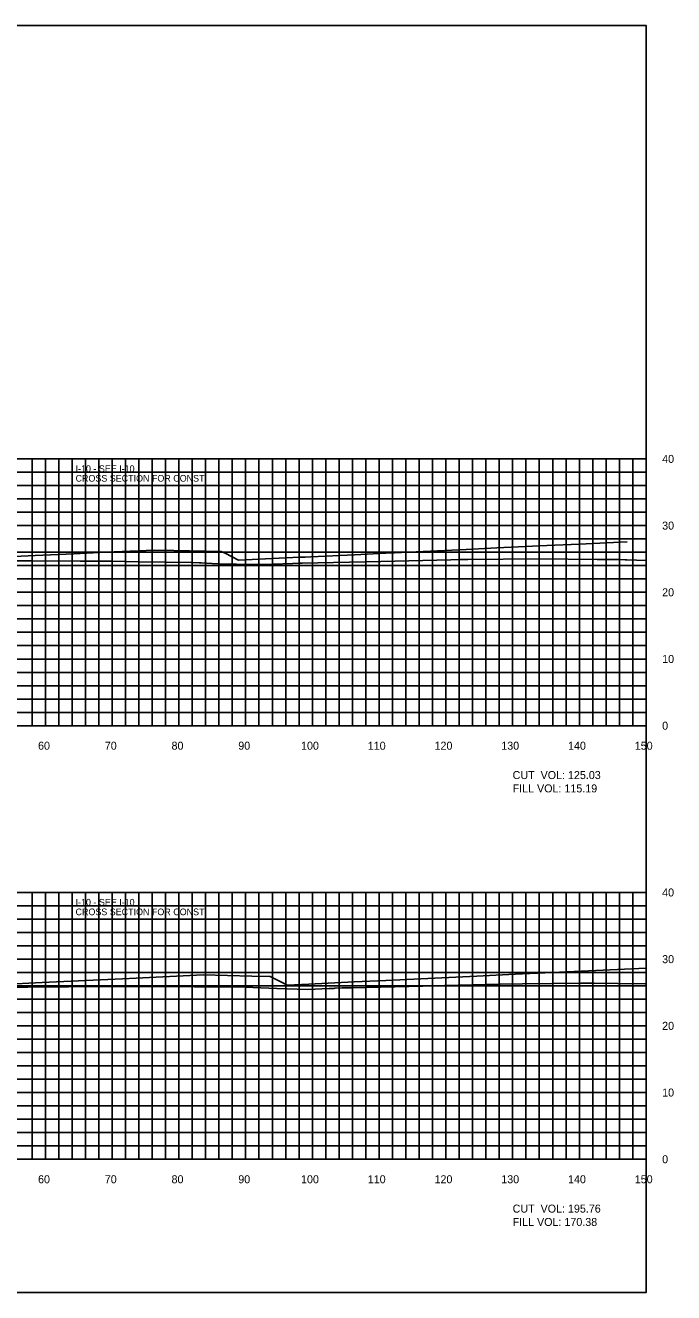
# Model space of a CAD drawing. Extents: x 1797652 to 1804159, y 242516 to 246906.
# Drawn here: x 1804061.5 to 1804158.6, y 242516 to 242706 of the extents above; entities that cross this region are included whole.
import ezdxf

# ---------------------------------------------------------------- set-up
doc = ezdxf.new("R2010")
doc.units = 0
for name, color, linetype in [('10', 7, 'Continuous'), ('3', 7, 'Continuous'), ('31', 7, 'Continuous'), ('60', 7, 'Continuous'), ('CL-CNST', 7, 'Continuous'), ('Level 62', 7, 'Continuous'), ('M-ROADS', 7, 'Continuous')]:
    doc.layers.add(name, color=color, linetype=linetype)

msp = doc.modelspace()

# ---------------------------------------------------------------- linework, layer by layer
msp.add_lwpolyline([(1803854.49, 242516), (1804154.49, 242516), (1804154.49, 242706), (1803854.49, 242706)], close=True)
at = {"layer": '60'}
for p, q in [((1804154.49, 242601), (1804154.49, 242641)), ((1804154.55, 242641), (1804154.49, 242641)), ((1804154.55, 242631), (1804154.49, 242631)), ((1804154.55, 242621), (1804154.49, 242621)), ((1804154.55, 242611), (1804154.49, 242611)), ((1803854.49, 242601), (1804154.49, 242601)), ((1804064.49, 242600.94), (1804064.49, 242601)), ((1804074.49, 242600.94), (1804074.49, 242601)), ((1804084.49, 242600.94), (1804084.49, 242601)), ((1804094.49, 242600.94), (1804094.49, 242601)), ((1804104.49, 242600.94), (1804104.49, 242601)), ((1804114.49, 242600.94), (1804114.49, 242601)), ((1804124.49, 242600.94), (1804124.49, 242601)), ((1804134.49, 242600.94), (1804134.49, 242601)), ((1804144.49, 242600.94), (1804144.49, 242601)), ((1804154.49, 242600.94), (1804154.49, 242601)), ((1804154.55, 242601), (1804154.49, 242601)), ((1804154.49, 242536), (1804154.49, 242576)), ((1804154.55, 242576), (1804154.49, 242576)), ((1804154.55, 242566), (1804154.49, 242566)), ((1804154.55, 242556), (1804154.49, 242556)), ((1804154.55, 242546), (1804154.49, 242546)), ((1803854.49, 242536), (1804154.49, 242536)), ((1804064.49, 242535.94), (1804064.49, 242536)), ((1804074.49, 242535.94), (1804074.49, 242536)), ((1804084.49, 242535.94), (1804084.49, 242536)), ((1804094.49, 242535.94), (1804094.49, 242536)), ((1804104.49, 242535.94), (1804104.49, 242536)), ((1804114.49, 242535.94), (1804114.49, 242536)), ((1804124.49, 242535.94), (1804124.49, 242536)), ((1804134.49, 242535.94), (1804134.49, 242536)), ((1804144.49, 242535.94), (1804144.49, 242536)), ((1804154.49, 242535.94), (1804154.49, 242536)), ((1804154.55, 242536), (1804154.49, 242536))]:
    msp.add_line(p, q, dxfattribs=at)
at = {"layer": 'CL-CNST'}
for points in [[(1804056.68, 242626.21), (1804062.96, 242626.5), (1804068.74, 242626.77), (1804073.61, 242627), (1804080.81, 242627.34), (1804083.71, 242627.27), (1804090.82, 242627.11), (1804091.42, 242626.85), (1804093.4, 242625.82), (1804102.54, 242626.25), (1804103.43, 242626.29), (1804104.27, 242626.33), (1804110.81, 242626.64), (1804115.49, 242626.86), (1804116.77, 242626.92), (1804127.55, 242627.43), (1804132.12, 242627.65), (1804139.61, 242628), (1804144.46, 242628.23), (1804151.67, 242628.57)], [(1804052.05, 242561.92), (1804063.99, 242562.49), (1804065.08, 242562.54), (1804076.06, 242563.06), (1804078.1, 242563.16), (1804088.13, 242563.64), (1804095.42, 242563.47), (1804098.18, 242563.41), (1804099.94, 242562.5), (1804100.7, 242562.11), (1804103.97, 242562.26), (1804110.76, 242562.59), (1804115.51, 242562.81), (1804122.82, 242563.16), (1804129.15, 242563.46), (1804134.89, 242563.73), (1804140.42, 242563.99), (1804146.96, 242564.3), (1804154.48, 242564.66), (1804154.49, 242564.66)]]:
    msp.add_lwpolyline(points, dxfattribs=at)
at = {"layer": 'Level 62'}
for p, q in [((1803854.49, 242641), (1804154.49, 242641)), ((1804062.49, 242601), (1804062.49, 242641)), ((1804064.49, 242601), (1804064.49, 242641)), ((1804066.49, 242601), (1804066.49, 242641)), ((1804068.49, 242601), (1804068.49, 242641)), ((1804070.49, 242601), (1804070.49, 242641)), ((1804072.49, 242601), (1804072.49, 242641)), ((1804074.49, 242601), (1804074.49, 242641)), ((1804076.49, 242601), (1804076.49, 242641)), ((1804078.49, 242601), (1804078.49, 242641)), ((1804080.49, 242601), (1804080.49, 242641)), ((1804082.49, 242601), (1804082.49, 242641)), ((1804084.49, 242601), (1804084.49, 242641)), ((1804086.49, 242601), (1804086.49, 242641)), ((1804088.49, 242601), (1804088.49, 242641)), ((1804090.49, 242601), (1804090.49, 242641)), ((1804092.49, 242601), (1804092.49, 242641)), ((1804094.49, 242601), (1804094.49, 242641)), ((1804096.49, 242601), (1804096.49, 242641)), ((1804098.49, 242601), (1804098.49, 242641)), ((1804100.49, 242601), (1804100.49, 242641)), ((1804102.49, 242601), (1804102.49, 242641)), ((1804104.49, 242601), (1804104.49, 242641)), ((1804106.49, 242601), (1804106.49, 242641)), ((1804108.49, 242601), (1804108.49, 242641)), ((1804110.49, 242601), (1804110.49, 242641)), ((1804112.49, 242601), (1804112.49, 242641)), ((1804114.49, 242601), (1804114.49, 242641)), ((1804116.49, 242601), (1804116.49, 242641)), ((1804118.49, 242601), (1804118.49, 242641)), ((1804120.49, 242601), (1804120.49, 242641)), ((1804122.49, 242601), (1804122.49, 242641)), ((1804124.49, 242601), (1804124.49, 242641)), ((1804126.49, 242601), (1804126.49, 242641)), ((1804128.49, 242601), (1804128.49, 242641)), ((1804130.49, 242601), (1804130.49, 242641)), ((1804132.49, 242601), (1804132.49, 242641)), ((1804134.49, 242601), (1804134.49, 242641)), ((1804136.49, 242601), (1804136.49, 242641)), ((1804138.49, 242601), (1804138.49, 242641)), ((1804140.49, 242601), (1804140.49, 242641)), ((1804142.49, 242601), (1804142.49, 242641)), ((1804144.49, 242601), (1804144.49, 242641)), ((1804146.49, 242601), (1804146.49, 242641)), ((1804148.49, 242601), (1804148.49, 242641)), ((1804150.49, 242601), (1804150.49, 242641)), ((1804152.49, 242601), (1804152.49, 242641)), ((1804154.49, 242601), (1804154.49, 242641)), ((1803854.49, 242639), (1804154.49, 242639)), ((1803854.49, 242637), (1804154.49, 242637)), ((1803854.49, 242635), (1804154.49, 242635)), ((1803854.49, 242633), (1804154.49, 242633)), ((1803854.49, 242631), (1804154.49, 242631)), ((1803854.49, 242629), (1804154.49, 242629)), ((1803854.49, 242627), (1804154.49, 242627)), ((1803854.49, 242625), (1804154.49, 242625)), ((1803854.49, 242623), (1804154.49, 242623)), ((1803854.49, 242621), (1804154.49, 242621)), ((1803854.49, 242619), (1804154.49, 242619)), ((1803854.49, 242617), (1804154.49, 242617)), ((1803854.49, 242615), (1804154.49, 242615)), ((1803854.49, 242613), (1804154.49, 242613)), ((1803854.49, 242611), (1804154.49, 242611)), ((1803854.49, 242609), (1804154.49, 242609)), ((1803854.49, 242607), (1804154.49, 242607)), ((1803854.49, 242605), (1804154.49, 242605)), ((1803854.49, 242603), (1804154.49, 242603)), ((1803854.49, 242601), (1804154.49, 242601)), ((1803854.49, 242576), (1804154.49, 242576)), ((1804062.49, 242536), (1804062.49, 242576)), ((1804064.49, 242536), (1804064.49, 242576)), ((1804066.49, 242536), (1804066.49, 242576)), ((1804068.49, 242536), (1804068.49, 242576)), ((1804070.49, 242536), (1804070.49, 242576)), ((1804072.49, 242536), (1804072.49, 242576)), ((1804074.49, 242536), (1804074.49, 242576)), ((1804076.49, 242536), (1804076.49, 242576)), ((1804078.49, 242536), (1804078.49, 242576)), ((1804080.49, 242536), (1804080.49, 242576)), ((1804082.49, 242536), (1804082.49, 242576)), ((1804084.49, 242536), (1804084.49, 242576)), ((1804086.49, 242536), (1804086.49, 242576)), ((1804088.49, 242536), (1804088.49, 242576)), ((1804090.49, 242536), (1804090.49, 242576)), ((1804092.49, 242536), (1804092.49, 242576)), ((1804094.49, 242536), (1804094.49, 242576)), ((1804096.49, 242536), (1804096.49, 242576)), ((1804098.49, 242536), (1804098.49, 242576)), ((1804100.49, 242536), (1804100.49, 242576)), ((1804102.49, 242536), (1804102.49, 242576)), ((1804104.49, 242536), (1804104.49, 242576)), ((1804106.49, 242536), (1804106.49, 242576)), ((1804108.49, 242536), (1804108.49, 242576)), ((1804110.49, 242536), (1804110.49, 242576)), ((1804112.49, 242536), (1804112.49, 242576)), ((1804114.49, 242536), (1804114.49, 242576)), ((1804116.49, 242536), (1804116.49, 242576)), ((1804118.49, 242536), (1804118.49, 242576)), ((1804120.49, 242536), (1804120.49, 242576)), ((1804122.49, 242536), (1804122.49, 242576)), ((1804124.49, 242536), (1804124.49, 242576)), ((1804126.49, 242536), (1804126.49, 242576)), ((1804128.49, 242536), (1804128.49, 242576)), ((1804130.49, 242536), (1804130.49, 242576)), ((1804132.49, 242536), (1804132.49, 242576)), ((1804134.49, 242536), (1804134.49, 242576)), ((1804136.49, 242536), (1804136.49, 242576)), ((1804138.49, 242536), (1804138.49, 242576)), ((1804140.49, 242536), (1804140.49, 242576)), ((1804142.49, 242536), (1804142.49, 242576)), ((1804144.49, 242536), (1804144.49, 242576)), ((1804146.49, 242536), (1804146.49, 242576)), ((1804148.49, 242536), (1804148.49, 242576)), ((1804150.49, 242536), (1804150.49, 242576)), ((1804152.49, 242536), (1804152.49, 242576)), ((1804154.49, 242536), (1804154.49, 242576)), ((1803854.49, 242574), (1804154.49, 242574)), ((1803854.49, 242572), (1804154.49, 242572)), ((1803854.49, 242570), (1804154.49, 242570)), ((1803854.49, 242568), (1804154.49, 242568)), ((1803854.49, 242566), (1804154.49, 242566)), ((1803854.49, 242564), (1804154.49, 242564)), ((1803854.49, 242562), (1804154.49, 242562)), ((1803854.49, 242560), (1804154.49, 242560)), ((1803854.49, 242558), (1804154.49, 242558)), ((1803854.49, 242556), (1804154.49, 242556)), ((1803854.49, 242554), (1804154.49, 242554)), ((1803854.49, 242552), (1804154.49, 242552)), ((1803854.49, 242550), (1804154.49, 242550)), ((1803854.49, 242548), (1804154.49, 242548)), ((1803854.49, 242546), (1804154.49, 242546)), ((1803854.49, 242544), (1804154.49, 242544)), ((1803854.49, 242542), (1804154.49, 242542)), ((1803854.49, 242540), (1804154.49, 242540)), ((1803854.49, 242538), (1804154.49, 242538)), ((1803854.49, 242536), (1804154.49, 242536))]:
    msp.add_line(p, q, dxfattribs=at)
at = {"layer": 'M-ROADS'}
for points in [[(1804059.93, 242625.73), (1804062.42, 242625.73), (1804069.68, 242625.68), (1804074.51, 242625.65), (1804078.44, 242625.59), (1804086.34, 242625.48), (1804086.48, 242625.48), (1804087.59, 242625.42), (1804087.82, 242625.41), (1804089.46, 242625.32), (1804091.22, 242625.23), (1804093.14, 242625.22), (1804098.01, 242625.19), (1804098.54, 242625.22), (1804101.52, 242625.33), (1804101.56, 242625.33), (1804102.54, 242625.35), (1804102.75, 242625.36), (1804102.76, 242625.36), (1804102.96, 242625.36), (1804114.76, 242625.64), (1804125.21, 242625.87), (1804126.43, 242625.9), (1804127.8, 242625.92), (1804138.44, 242626.02), (1804147.14, 242625.93), (1804150.35, 242625.9), (1804151.35, 242625.87), (1804151.6, 242625.86), (1804154.49, 242625.76)], [(1804056.28, 242561.74), (1804061.85, 242561.79), (1804067.96, 242561.84), (1804078.89, 242561.89), (1804080.18, 242561.9), (1804086.85, 242561.87), (1804091.69, 242561.87), (1804092.25, 242561.86), (1804092.94, 242561.84), (1804094.37, 242561.79), (1804096.76, 242561.71), (1804099.18, 242561.62), (1804103.75, 242561.45), (1804107, 242561.6), (1804107.68, 242561.62), (1804107.85, 242561.63), (1804108.93, 242561.68), (1804110.5, 242561.71), (1804121.04, 242561.97), (1804124.28, 242562.06), (1804130.43, 242562.19), (1804131.87, 242562.22), (1804132.62, 242562.24), (1804135.97, 242562.29), (1804144.71, 242562.42), (1804146.7, 242562.39), (1804150.25, 242562.35), (1804154.33, 242562.3), (1804154.49, 242562.3)]]:
    msp.add_lwpolyline(points, dxfattribs=at)

# ---------------------------------------------------------------- texts
at = {"layer": '10'}
for s, p in [('60', (1804063.39, 242597.4)), ('70', (1804073.39, 242597.4)), ('80', (1804083.39, 242597.4)), ('90', (1804093.39, 242597.4)), ('100', (1804102.79, 242597.4)), ('110', (1804112.79, 242597.4)), ('120', (1804122.79, 242597.4)), ('130', (1804132.79, 242597.4)), ('140', (1804142.79, 242597.4)), ('150', (1804152.79, 242597.4)), ('CUT  VOL: 125.03', (1804134.49, 242593)), ('FILL VOL: 115.19', (1804134.49, 242591)), ('60', (1804063.39, 242532.4)), ('70', (1804073.39, 242532.4)), ('80', (1804083.39, 242532.4)), ('90', (1804093.39, 242532.4)), ('100', (1804102.79, 242532.4)), ('110', (1804112.79, 242532.4)), ('120', (1804122.79, 242532.4)), ('130', (1804132.79, 242532.4)), ('140', (1804142.79, 242532.4)), ('150', (1804152.79, 242532.4)), ('CUT  VOL: 195.76', (1804134.49, 242528)), ('FILL VOL: 170.38', (1804134.49, 242526))]:
    msp.add_text(s, height=1.2, dxfattribs=at).set_placement(p)
at = {"layer": '3'}
for s, p in [('I-10 - SEE I-10', (1804069.01, 242639.03)), ('CROSS SECTION FOR CONST ', (1804069.01, 242637.59)), ('I-10 - SEE I-10', (1804069.01, 242574.03)), ('CROSS SECTION FOR CONST ', (1804069.01, 242572.59))]:
    msp.add_text(s, height=1, dxfattribs=at).set_placement(p)
at = {"layer": '31'}
for s, p in [('40', (1804156.89, 242640.4)), ('30', (1804156.89, 242630.4)), ('20', (1804156.89, 242620.4)), ('10', (1804156.89, 242610.4)), ('0', (1804156.89, 242600.4)), ('40', (1804156.89, 242575.4)), ('30', (1804156.89, 242565.4)), ('20', (1804156.89, 242555.4)), ('10', (1804156.89, 242545.4)), ('0', (1804156.89, 242535.4))]:
    msp.add_text(s, height=1.2, dxfattribs=at).set_placement(p)

doc.saveas('drawing.dxf')
